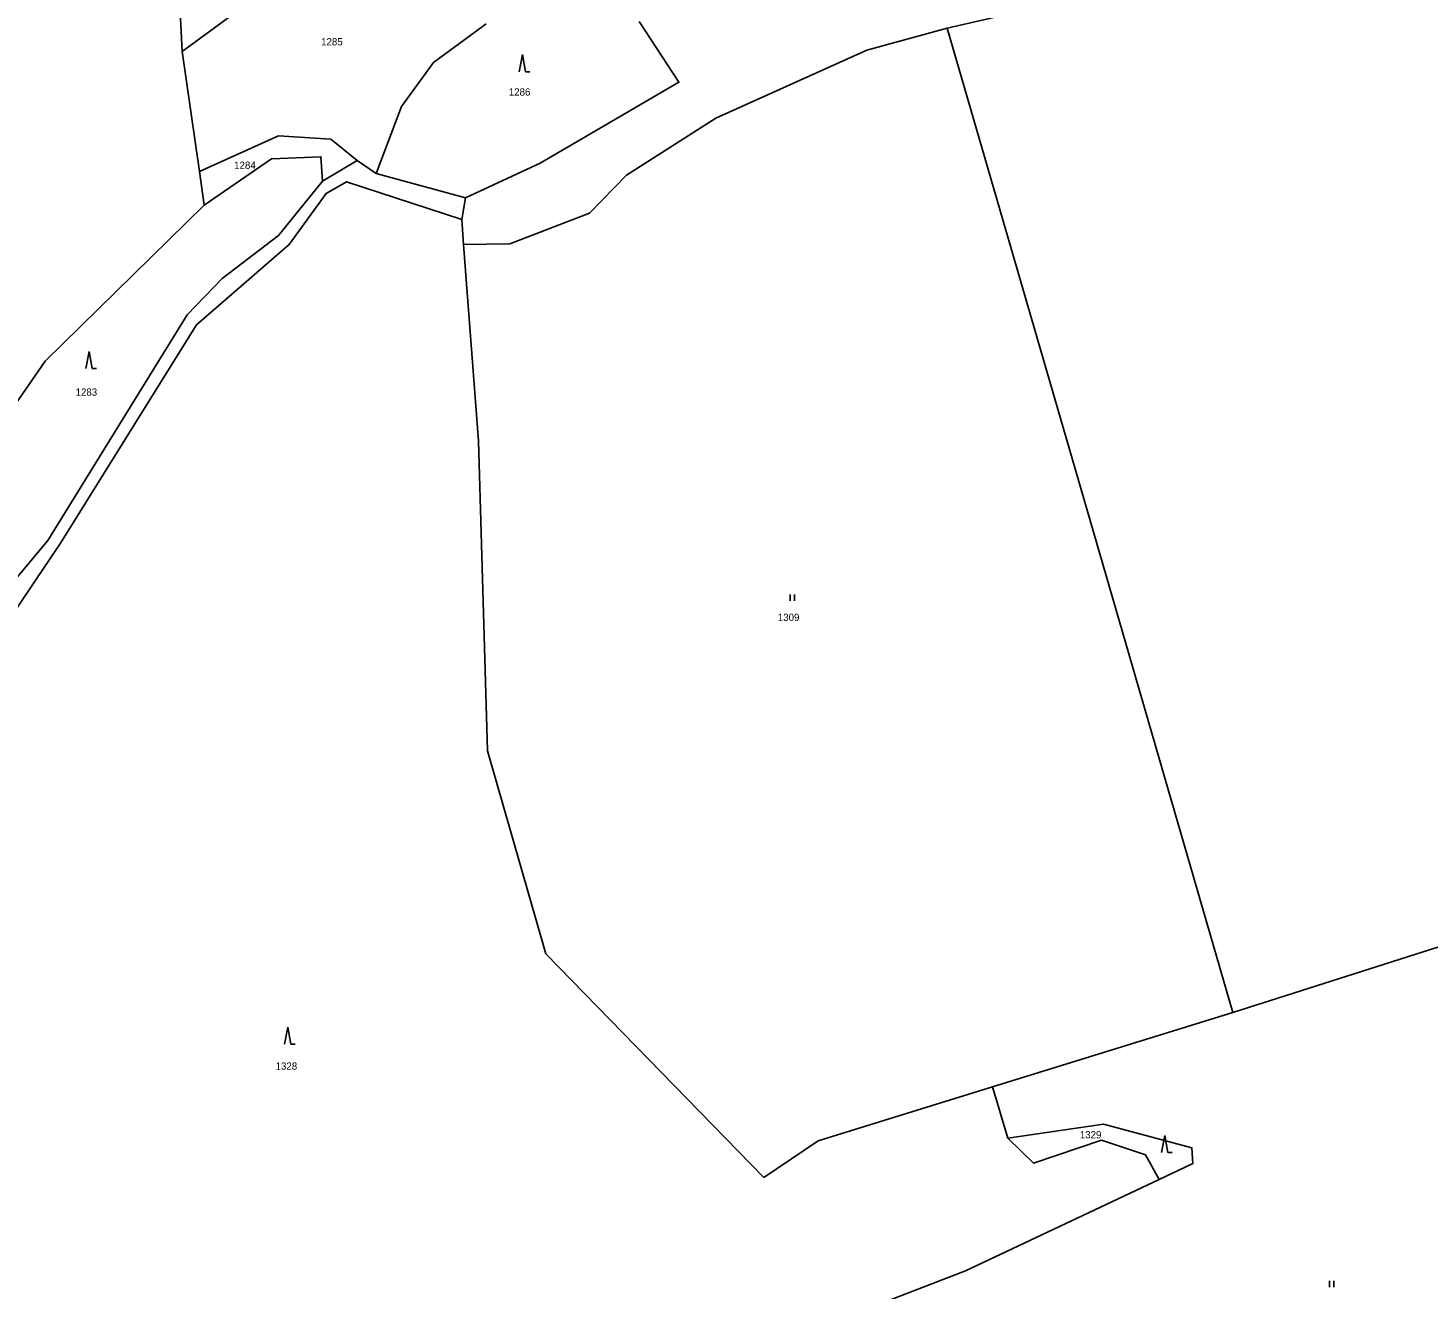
# Model space of a CAD drawing. Extents: x -520431 to -517205, y -1075927 to -1074013.
# Drawn here: x -518704.2 to -518376.5, y -1075237.3 to -1074942.1 of the extents above; entities that cross this region are included whole.
import ezdxf

# ---------------------------------------------------------------- set-up
doc = ezdxf.new("R2010")
doc.units = 0
for name, color, linetype in [('Hranice parcel', 7, 'Continuous'), ('Parcelní čísla', 7, 'Continuous'), ('Značky kultur', 7, 'Continuous')]:
    doc.layers.add(name, color=color, linetype=linetype)

msp = doc.modelspace()

# ---------------------------------------------------------------- linework, layer by layer
at = {"layer": 'Hranice parcel'}
for p, q in [((-518668.09, -1074947.61), (-518611.24, -1074905.77)), ((-518668.09, -1074947.61), (-518664.04, -1074975.7)), ((-518664.04, -1074975.7), (-518662.91, -1074983.55)), ((-518635.26, -1074977.97), (-518627.09, -1074973.12)), ((-518627.09, -1074973.12), (-518622.68, -1074976.16)), ((-518622.68, -1074976.16), (-518601.76, -1074981.84)), ((-518601.76, -1074981.84), (-518602.64, -1074986.93)), ((-518602.64, -1074986.93), (-518602.2, -1074992.79)), ((-518478.41, -1075190.02), (-518422.14, -1075172.6)), ((-518474.82, -1075202.03), (-518478.41, -1075190.02))]:
    msp.add_line(p, q, dxfattribs=at)
for points in [[(-518684.73, -1074869.87), (-518669.52, -1074919.69), (-518668.09, -1074947.61)], [(-518488.98, -1074942.15), (-518375.2, -1074916), (-518252.8, -1074891.92), (-518160.47, -1074874.79), (-518153.83, -1074875.61), (-518134.22, -1074871.66), (-518128.73, -1074868.52), (-518116.84, -1074871.29), (-518110.95, -1074881.98)], [(-518622.68, -1074976.16), (-518616.71, -1074960.47), (-518609.29, -1074950.18), (-518596.9, -1074941.15)], [(-518602.2, -1074992.79), (-518591.4, -1074992.6), (-518572.73, -1074985.41), (-518564.05, -1074976.58), (-518543.2, -1074963.19), (-518507.82, -1074947.3), (-518488.98, -1074942.15)], [(-518561.09, -1074940.54), (-518551.81, -1074954.79), (-518584.27, -1074973.77), (-518601.76, -1074981.84)], [(-518488.98, -1074942.15), (-518455.56, -1075057.38), (-518422.14, -1075172.6)], [(-518627.09, -1074973.12), (-518633.28, -1074968.13), (-518645.55, -1074967.36), (-518664.04, -1074975.7)], [(-518635.26, -1074977.97), (-518635.6, -1074972.24), (-518647.15, -1074972.75), (-518662.91, -1074983.55)], [(-518714.23, -1075079.58), (-518699.53, -1075062.06), (-518666.95, -1075009.26), (-518658.75, -1075000.75), (-518645.56, -1074990.66), (-518635.26, -1074977.97)], [(-518602.64, -1074986.93), (-518629.6, -1074978.08), (-518634.38, -1074980.83), (-518643.01, -1074992.79), (-518664.74, -1075011.55), (-518696.55, -1075062.68), (-518709.51, -1075082)], [(-518662.91, -1074983.55), (-518700.12, -1075020.1), (-518714.7, -1075041.05), (-518713.95, -1075070.56)], [(-518602.2, -1074992.79), (-518598.7, -1075038.77), (-518596.61, -1075111.33), (-518582.95, -1075158.83), (-518531.92, -1075211.2), (-518519.19, -1075202.64), (-518478.41, -1075190.02)], [(-518422.14, -1075172.6), (-518258.38, -1075120.35), (-518094.89, -1075068.19)], [(-518439.42, -1075211.7), (-518431.49, -1075207.95), (-518431.71, -1075204.28), (-518452.46, -1075198.76), (-518474.82, -1075202.03)], [(-518439.42, -1075211.7), (-518442.62, -1075205.88), (-518452.9, -1075202.51), (-518468.79, -1075207.84), (-518474.82, -1075202.03)], [(-518534.01, -1075252.15), (-518484.75, -1075233.11), (-518439.42, -1075211.7)]]:
    msp.add_lwpolyline(points, dxfattribs=at)
at = {"layer": 'Značky kultur'}
for p, q in [((-518588.44, -1074948.32), (-518589.19, -1074952.32)), ((-518587.69, -1074952.32), (-518588.44, -1074948.32)), ((-518587.69, -1074952.32), (-518586.69, -1074952.32)), ((-518689.88, -1075017.85), (-518690.63, -1075021.85)), ((-518689.13, -1075021.85), (-518689.88, -1075017.85)), ((-518689.13, -1075021.85), (-518688.13, -1075021.85)), ((-518525.75, -1075076.22), (-518525.75, -1075074.72)), ((-518524.75, -1075076.22), (-518524.75, -1075074.72)), ((-518643.37, -1075176), (-518644.12, -1075180)), ((-518642.62, -1075180), (-518643.37, -1075176)), ((-518642.62, -1075180), (-518641.62, -1075180)), ((-518438.1, -1075201.4), (-518438.85, -1075205.4)), ((-518437.35, -1075205.4), (-518438.1, -1075201.4)), ((-518437.35, -1075205.4), (-518436.35, -1075205.4)), ((-518399.5, -1075236.88), (-518399.5, -1075235.38)), ((-518398.5, -1075236.88), (-518398.5, -1075235.38))]:
    msp.add_line(p, q, dxfattribs=at)

# ---------------------------------------------------------------- texts
at = {"layer": 'Parcelní čísla'}
for s, p in [('1285', (-518635.57, -1074946.17)), ('1286', (-518591.63, -1074957.92)), ('1284', (-518655.92, -1074975.06)), ('1283', (-518693.04, -1075028.19)), ('1309', (-518528.66, -1075080.92)), ('1328', (-518646.22, -1075185.99)), ('1329', (-518457.97, -1075202.06))]:
    msp.add_text(s, height=1.7, dxfattribs=at).set_placement(p)

doc.saveas('drawing.dxf')
